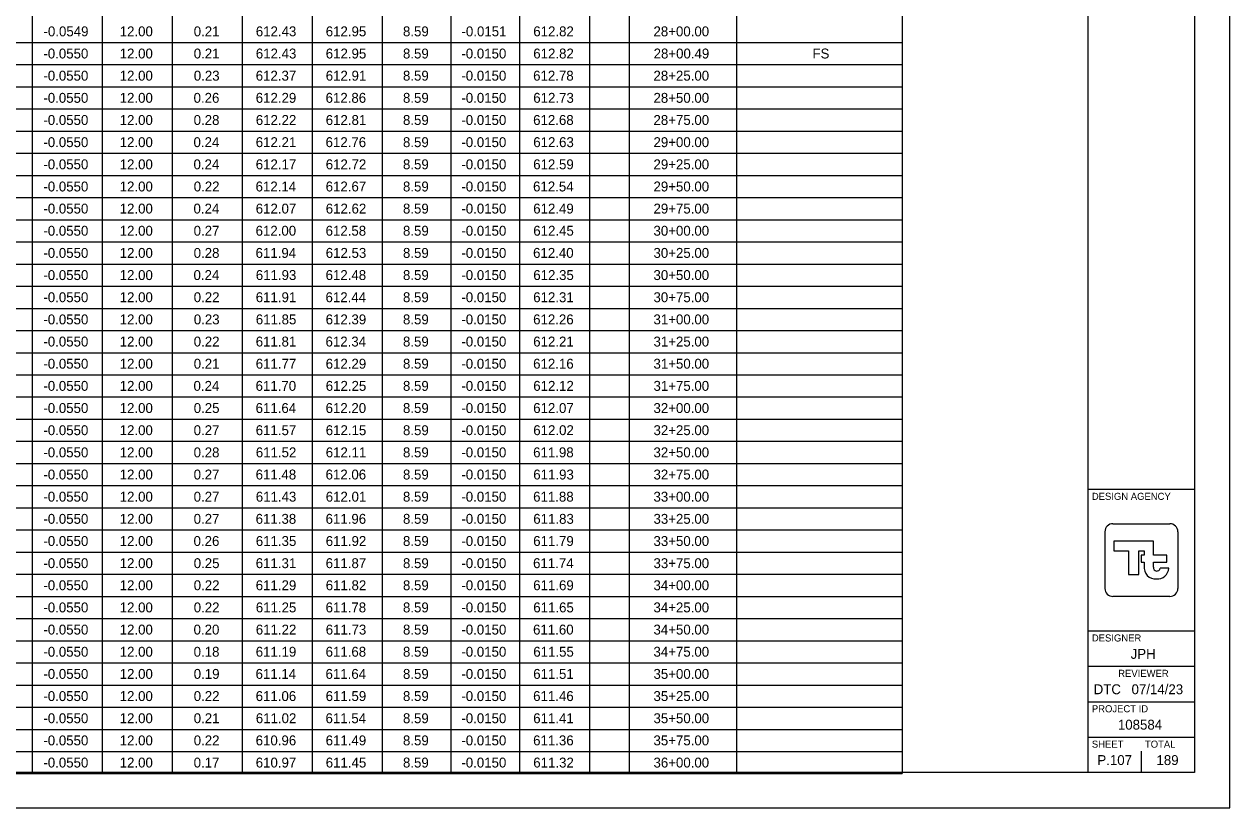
# Model space of a CAD drawing. Extents: x 0 to 34, y 0 to 22.
# Drawn here: x 16.97 to 34, y 0 to 11.07 of the extents above; entities that cross this region are included whole.
import ezdxf

# ---------------------------------------------------------------- set-up
doc = ezdxf.new("R2010")
doc.units = 0
for name, color, linetype in [('SH_Border', 7, 'Continuous'), ('SH_Cut_Line', 7, 'Continuous'), ('SH_Data', 7, 'Continuous'), ('SH_Text', 7, 'Continuous')]:
    doc.layers.add(name, color=color, linetype=linetype)

msp = doc.modelspace()

# ---------------------------------------------------------------- linework, layer by layer
at = {"layer": 'SH_Border'}
for p, q in [((32, 0.5), (32, 21.5)), ((32, 4.5), (33.5, 4.5)), ((32, 2.5), (33.5, 2.5)), ((32, 2), (33.5, 2)), ((32, 1.5), (33.5, 1.5)), ((32, 1), (33.5, 1))]:
    msp.add_line(p, q, dxfattribs=at)
msp.add_lwpolyline([(1.5, 21.5), (33.5, 21.5), (33.5, 0.5), (1.5, 0.5)], close=True, dxfattribs=at)
at = {"layer": 'SH_Cut_Line'}
msp.add_lwpolyline([(0, 0), (34, 0), (34, 22), (0, 22)], close=True, dxfattribs=at)
at = {"layer": 'SH_Data'}
for p, q in [((32.75, 3.5), (32.75, 3.5)), ((32.791, 3.415), (32.791, 3.415)), ((33.136, 3.385), (33.015, 3.385)), ((32.75, 0.5), (32.75, 0.8)), ((32.375, 0.675), (32.375, 0.675))]:
    msp.add_line(p, q, dxfattribs=at)
for points in [[(32.348, 4.014), (33.152, 4.014)], [(32.236, 3.099), (32.236, 3.901)], [(32.922, 3.399), (32.922, 3.47), (33.107, 3.47), (33.107, 3.568), (32.922, 3.568), (32.922, 3.768), (32.361, 3.768), (32.361, 3.632), (32.566, 3.632), (32.566, 3.294), (32.715, 3.294), (32.715, 3.63), (32.79, 3.63), (32.79, 3.568), (32.748, 3.568), (32.748, 3.47), (32.79, 3.47), (32.79, 3.415), (32.791, 3.415)], [(33.264, 3.901), (33.264, 3.099)], [(33.152, 2.986), (32.348, 2.986)]]:
    msp.add_lwpolyline(points, dxfattribs=at)
for centre, radius, start, end in [((32.348, 3.901), 0.113, 90, 180), ((33.152, 3.901), 0.113, 360, 90), ((32.949, 3.392), 0.16, 171.8856, 274.8323), ((32.968, 3.392), 0.0473, 171.8856, 350.9243), ((32.976, 3.392), 0.16, 265.1677, 357.3201), ((32.348, 3.099), 0.113, 180, 270), ((33.152, 3.099), 0.113, 270, 360)]:
    msp.add_arc(centre, radius, start, end, dxfattribs=at)
at = {"layer": 'SH_Text'}
for p, q in [((29.368, 21.5), (29.368, 0.484)), ((24.954, 20.396), (24.954, 0.484)), ((27.029, 20.396), (27.029, 0.484)), ((19.057, 19.853), (19.057, 0.484)), ((22.022, 19.853), (22.022, 0.484)), ((25.514, 19.853), (25.514, 0.484)), ((17.081, 19.54), (17.081, 0.484)), ((18.069, 19.54), (18.069, 0.484)), ((20.046, 19.54), (20.046, 0.484)), ((21.034, 19.54), (21.034, 0.484)), ((22.994, 19.54), (22.994, 0.484)), ((23.966, 19.54), (23.966, 0.484)), ((4.135, 10.811), (29.368, 10.811)), ((4.135, 10.498), (29.368, 10.498)), ((4.135, 10.185), (29.368, 10.185)), ((4.135, 9.872), (29.368, 9.872)), ((4.135, 9.559), (29.368, 9.559)), ((4.135, 9.246), (29.368, 9.246)), ((4.135, 8.933), (29.368, 8.933)), ((4.135, 8.62), (29.368, 8.62)), ((4.135, 8.307), (29.368, 8.307)), ((4.135, 7.994), (29.368, 7.994)), ((4.135, 7.681), (29.368, 7.681)), ((4.135, 7.368), (29.368, 7.368)), ((4.135, 7.055), (29.368, 7.055)), ((4.135, 6.742), (29.368, 6.742)), ((4.135, 6.429), (29.368, 6.429)), ((4.135, 6.116), (29.368, 6.116)), ((4.135, 5.804), (29.368, 5.804)), ((4.135, 5.491), (29.368, 5.491)), ((4.135, 5.178), (29.368, 5.178)), ((4.135, 4.865), (29.368, 4.865)), ((4.135, 4.552), (29.368, 4.552)), ((4.135, 4.239), (29.368, 4.239)), ((4.135, 3.926), (29.368, 3.926)), ((4.135, 3.613), (29.368, 3.613)), ((4.135, 3.3), (29.368, 3.3)), ((4.135, 2.987), (29.368, 2.987)), ((4.135, 2.674), (29.368, 2.674)), ((4.135, 2.361), (29.368, 2.361)), ((4.135, 2.048), (29.368, 2.048)), ((4.135, 1.735), (29.368, 1.735)), ((4.135, 1.422), (29.368, 1.422)), ((4.135, 1.109), (29.368, 1.109)), ((4.135, 0.796), (29.368, 0.796)), ((4.135, 0.484), (29.368, 0.484))]:
    msp.add_line(p, q, dxfattribs=at)

# ---------------------------------------------------------------- texts
at = {"layer": 'SH_Data'}
for s, height, p in [('DESIGN AGENCY', 0.1, (32.05, 4.35)), ('DESIGNER', 0.1, (32.05, 2.35)), ('JPH', 0.14, (32.598, 2.105)), ('REVIEWER', 0.1, (32.422, 1.85)), ('DTC', 0.14, (32.076, 1.605)), ('07/14/23', 0.14, (32.611, 1.605)), ('PROJECT ID', 0.1, (32.05, 1.35)), ('108584', 0.14, (32.418, 1.105)), ('SHEET', 0.1, (32.05, 0.85)), ('TOTAL', 0.1, (32.8, 0.85)), ('P.107', 0.14, (32.128, 0.605)), ('189', 0.14, (32.963, 0.605))]:
    msp.add_text(s, height=height, dxfattribs=at).set_placement(p)
at = {"layer": 'SH_Text'}
for s, p in [('-0.0549', (17.24, 10.897)), ('12.00', (18.316, 10.897)), ('0.21', (19.362, 10.897)), ('612.43', (20.239, 10.897)), ('612.95', (21.227, 10.897)), ('8.59', (22.318, 10.897)), ('-0.0151', (23.145, 10.897)), ('612.82', (24.159, 10.897)), ('28+00.00', (25.857, 10.897)), ('-0.0550', (17.238, 10.584)), ('12.00', (18.316, 10.584)), ('0.21', (19.362, 10.584)), ('612.43', (20.239, 10.584)), ('612.95', (21.227, 10.584)), ('8.59', (22.318, 10.584)), ('-0.0150', (23.143, 10.584)), ('612.82', (24.159, 10.584)), ('28+00.49', (25.859, 10.584)), ('FS', (28.103, 10.584)), ('-0.0550', (17.238, 10.271)), ('12.00', (18.316, 10.271)), ('0.23', (19.363, 10.271)), ('612.37', (20.238, 10.271)), ('612.91', (21.227, 10.271)), ('8.59', (22.318, 10.271)), ('-0.0150', (23.143, 10.271)), ('612.78', (24.157, 10.271)), ('28+25.00', (25.857, 10.271)), ('-0.0550', (17.238, 9.958)), ('12.00', (18.316, 9.958)), ('0.26', (19.36, 9.958)), ('612.29', (20.238, 9.958)), ('612.86', (21.225, 9.958)), ('8.59', (22.318, 9.958)), ('-0.0150', (23.143, 9.958)), ('612.73', (24.159, 9.958)), ('28+50.00', (25.857, 9.958)), ('-0.0550', (17.238, 9.645)), ('12.00', (18.316, 9.645)), ('0.28', (19.361, 9.645)), ('612.22', (20.239, 9.645)), ('612.81', (21.227, 9.645)), ('8.59', (22.318, 9.645)), ('-0.0150', (23.143, 9.645)), ('612.68', (24.157, 9.645)), ('28+75.00', (25.857, 9.645)), ('-0.0550', (17.238, 9.332)), ('12.00', (18.316, 9.332)), ('0.24', (19.359, 9.332)), ('612.21', (20.238, 9.332)), ('612.76', (21.225, 9.332)), ('8.59', (22.318, 9.332)), ('-0.0150', (23.143, 9.332)), ('612.63', (24.159, 9.332)), ('29+00.00', (25.857, 9.332)), ('-0.0550', (17.238, 9.019)), ('12.00', (18.316, 9.019)), ('0.24', (19.359, 9.019)), ('612.17', (20.238, 9.019)), ('612.72', (21.227, 9.019)), ('8.59', (22.318, 9.019)), ('-0.0150', (23.143, 9.019)), ('612.59', (24.158, 9.019)), ('29+25.00', (25.857, 9.019)), ('-0.0550', (17.238, 8.706)), ('12.00', (18.316, 8.706)), ('0.22', (19.362, 8.706)), ('612.14', (20.236, 8.706)), ('612.67', (21.226, 8.706)), ('8.59', (22.318, 8.706)), ('-0.0150', (23.143, 8.706)), ('612.54', (24.156, 8.706)), ('29+50.00', (25.857, 8.706)), ('-0.0550', (17.238, 8.394)), ('12.00', (18.316, 8.394)), ('0.24', (19.359, 8.394)), ('612.07', (20.238, 8.394)), ('612.62', (21.227, 8.394)), ('8.59', (22.318, 8.394)), ('-0.0150', (23.143, 8.394)), ('612.49', (24.158, 8.394)), ('29+75.00', (25.857, 8.394)), ('-0.0550', (17.238, 8.081)), ('12.00', (18.316, 8.081)), ('0.27', (19.361, 8.081)), ('612.00', (20.236, 8.081)), ('612.58', (21.225, 8.081)), ('8.59', (22.318, 8.081)), ('-0.0150', (23.143, 8.081)), ('612.45', (24.159, 8.081)), ('30+00.00', (25.857, 8.081)), ('-0.0550', (17.238, 7.768)), ('12.00', (18.316, 7.768)), ('0.28', (19.361, 7.768)), ('611.94', (20.236, 7.768)), ('612.53', (21.227, 7.768)), ('8.59', (22.318, 7.768)), ('-0.0150', (23.143, 7.768)), ('612.40', (24.156, 7.768)), ('30+25.00', (25.857, 7.768)), ('-0.0550', (17.238, 7.455)), ('12.00', (18.316, 7.455)), ('0.24', (19.359, 7.455)), ('611.93', (20.239, 7.455)), ('612.48', (21.225, 7.455)), ('8.59', (22.318, 7.455)), ('-0.0150', (23.143, 7.455)), ('612.35', (24.159, 7.455)), ('30+50.00', (25.857, 7.455)), ('-0.0550', (17.238, 7.142)), ('12.00', (18.316, 7.142)), ('0.22', (19.362, 7.142)), ('611.91', (20.238, 7.142)), ('612.44', (21.224, 7.142)), ('8.59', (22.318, 7.142)), ('-0.0150', (23.143, 7.142)), ('612.31', (24.158, 7.142)), ('30+75.00', (25.857, 7.142)), ('-0.0550', (17.238, 6.829)), ('12.00', (18.316, 6.829)), ('0.23', (19.363, 6.829)), ('611.85', (20.239, 6.829)), ('612.39', (21.226, 6.829)), ('8.59', (22.318, 6.829)), ('-0.0150', (23.143, 6.829)), ('612.26', (24.157, 6.829)), ('31+00.00', (25.857, 6.829)), ('-0.0550', (17.238, 6.516)), ('12.00', (18.316, 6.516)), ('0.22', (19.362, 6.516)), ('611.81', (20.238, 6.516)), ('612.34', (21.224, 6.516)), ('8.59', (22.318, 6.516)), ('-0.0150', (23.143, 6.516)), ('612.21', (24.158, 6.516)), ('31+25.00', (25.857, 6.516)), ('-0.0550', (17.238, 6.203)), ('12.00', (18.316, 6.203)), ('0.21', (19.362, 6.203)), ('611.77', (20.238, 6.203)), ('612.29', (21.226, 6.203)), ('8.59', (22.318, 6.203)), ('-0.0150', (23.143, 6.203)), ('612.16', (24.157, 6.203)), ('31+50.00', (25.857, 6.203)), ('-0.0550', (17.238, 5.89)), ('12.00', (18.316, 5.89)), ('0.24', (19.359, 5.89)), ('611.70', (20.236, 5.89)), ('612.25', (21.227, 5.89)), ('8.59', (22.318, 5.89)), ('-0.0150', (23.143, 5.89)), ('612.12', (24.159, 5.89)), ('31+75.00', (25.857, 5.89)), ('-0.0550', (17.238, 5.577)), ('12.00', (18.316, 5.577)), ('0.25', (19.362, 5.577)), ('611.64', (20.236, 5.577)), ('612.20', (21.225, 5.577)), ('8.59', (22.318, 5.577)), ('-0.0150', (23.143, 5.577)), ('612.07', (24.158, 5.577)), ('32+00.00', (25.857, 5.577)), ('-0.0550', (17.238, 5.264)), ('12.00', (18.316, 5.264)), ('0.27', (19.361, 5.264)), ('611.57', (20.238, 5.264)), ('612.15', (21.227, 5.264)), ('8.59', (22.318, 5.264)), ('-0.0150', (23.143, 5.264)), ('612.02', (24.159, 5.264)), ('32+25.00', (25.857, 5.264)), ('-0.0550', (17.238, 4.951)), ('12.00', (18.316, 4.951)), ('0.28', (19.361, 4.951)), ('611.52', (20.239, 4.951)), ('612.11', (21.227, 4.951)), ('8.59', (22.318, 4.951)), ('-0.0150', (23.143, 4.951)), ('611.98', (24.157, 4.951)), ('32+50.00', (25.857, 4.951)), ('-0.0550', (17.238, 4.638)), ('12.00', (18.316, 4.638)), ('0.27', (19.361, 4.638)), ('611.48', (20.237, 4.638)), ('612.06', (21.225, 4.638)), ('8.59', (22.318, 4.638)), ('-0.0150', (23.143, 4.638)), ('611.93', (24.159, 4.638)), ('32+75.00', (25.857, 4.638)), ('-0.0550', (17.238, 4.325)), ('12.00', (18.316, 4.325)), ('0.27', (19.361, 4.325)), ('611.43', (20.239, 4.325)), ('612.01', (21.227, 4.325)), ('8.59', (22.318, 4.325)), ('-0.0150', (23.143, 4.325)), ('611.88', (24.157, 4.325)), ('33+00.00', (25.857, 4.325)), ('-0.0550', (17.238, 4.012)), ('12.00', (18.316, 4.012)), ('0.27', (19.361, 4.012)), ('611.38', (20.237, 4.012)), ('611.96', (21.225, 4.012)), ('8.59', (22.318, 4.012)), ('-0.0150', (23.143, 4.012)), ('611.83', (24.159, 4.012)), ('33+25.00', (25.857, 4.012)), ('-0.0550', (17.238, 3.699)), ('12.00', (18.316, 3.699)), ('0.26', (19.36, 3.699)), ('611.35', (20.239, 3.699)), ('611.92', (21.227, 3.699)), ('8.59', (22.318, 3.699)), ('-0.0150', (23.143, 3.699)), ('611.79', (24.158, 3.699)), ('33+50.00', (25.857, 3.699)), ('-0.0550', (17.238, 3.386)), ('12.00', (18.316, 3.386)), ('0.25', (19.362, 3.386)), ('611.31', (20.238, 3.386)), ('611.87', (21.226, 3.386)), ('8.59', (22.318, 3.386)), ('-0.0150', (23.143, 3.386)), ('611.74', (24.156, 3.386)), ('33+75.00', (25.857, 3.386)), ('-0.0550', (17.238, 3.074)), ('12.00', (18.316, 3.074)), ('0.22', (19.362, 3.074)), ('611.29', (20.238, 3.074)), ('611.82', (21.227, 3.074)), ('8.59', (22.318, 3.074)), ('-0.0150', (23.143, 3.074)), ('611.69', (24.158, 3.074)), ('34+00.00', (25.857, 3.074)), ('-0.0550', (17.238, 2.761)), ('12.00', (18.316, 2.761)), ('0.22', (19.362, 2.761)), ('611.25', (20.239, 2.761)), ('611.78', (21.225, 2.761)), ('8.59', (22.318, 2.761)), ('-0.0150', (23.143, 2.761)), ('611.65', (24.159, 2.761)), ('34+25.00', (25.857, 2.761)), ('-0.0550', (17.238, 2.448)), ('12.00', (18.316, 2.448)), ('0.20', (19.36, 2.448)), ('611.22', (20.239, 2.448)), ('611.73', (21.227, 2.448)), ('8.59', (22.318, 2.448)), ('-0.0150', (23.143, 2.448)), ('611.60', (24.156, 2.448)), ('34+50.00', (25.857, 2.448)), ('-0.0550', (17.238, 2.135)), ('12.00', (18.316, 2.135)), ('0.18', (19.361, 2.135)), ('611.19', (20.238, 2.135)), ('611.68', (21.225, 2.135)), ('8.59', (22.318, 2.135)), ('-0.0150', (23.143, 2.135)), ('611.55', (24.159, 2.135)), ('34+75.00', (25.857, 2.135)), ('-0.0550', (17.238, 1.822)), ('12.00', (18.316, 1.822)), ('0.19', (19.362, 1.822)), ('611.14', (20.236, 1.822)), ('611.64', (21.224, 1.822)), ('8.59', (22.318, 1.822)), ('-0.0150', (23.143, 1.822)), ('611.51', (24.158, 1.822)), ('35+00.00', (25.857, 1.822)), ('-0.0550', (17.238, 1.509)), ('12.00', (18.316, 1.509)), ('0.22', (19.362, 1.509)), ('611.06', (20.237, 1.509)), ('611.59', (21.226, 1.509)), ('8.59', (22.318, 1.509)), ('-0.0150', (23.143, 1.509)), ('611.46', (24.157, 1.509)), ('35+25.00', (25.857, 1.509)), ('-0.0550', (17.238, 1.196)), ('12.00', (18.316, 1.196)), ('0.21', (19.362, 1.196)), ('611.02', (20.239, 1.196)), ('611.54', (21.224, 1.196)), ('8.59', (22.318, 1.196)), ('-0.0150', (23.143, 1.196)), ('611.41', (24.158, 1.196)), ('35+50.00', (25.857, 1.196)), ('-0.0550', (17.238, 0.883)), ('12.00', (18.316, 0.883)), ('0.22', (19.362, 0.883)), ('610.96', (20.237, 0.883)), ('611.49', (21.226, 0.883)), ('8.59', (22.318, 0.883)), ('-0.0150', (23.143, 0.883)), ('611.36', (24.157, 0.883)), ('35+75.00', (25.857, 0.883)), ('-0.0550', (17.238, 0.57)), ('12.00', (18.316, 0.57)), ('0.17', (19.361, 0.57)), ('610.97', (20.238, 0.57)), ('611.45', (21.227, 0.57)), ('8.59', (22.318, 0.57)), ('-0.0150', (23.143, 0.57)), ('611.32', (24.159, 0.57)), ('36+00.00', (25.857, 0.57))]:
    msp.add_text(s, height=0.14, dxfattribs=at).set_placement(p)

doc.saveas('drawing.dxf')
